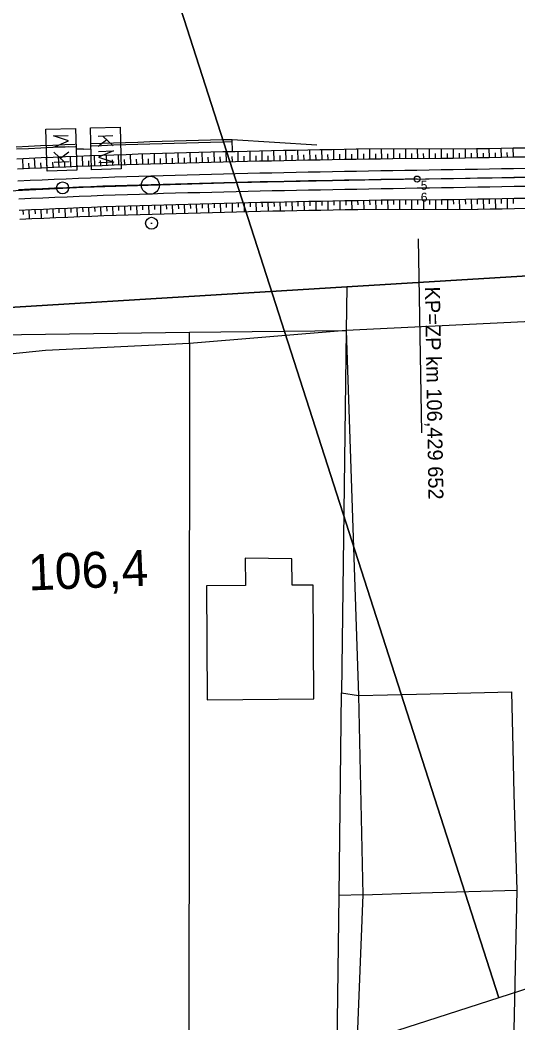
# Model space of a CAD drawing. Extents: x -758836 to -757729, y -1175316 to -1174366.
# Drawn here: x -758212.2 to -758170.6, y -1174834.3 to -1174750.5 of the extents above; entities that cross this region are included whole.
import ezdxf

# ---------------------------------------------------------------- set-up
doc = ezdxf.new("R2010")
doc.units = 0
for name, color, linetype in [('_NOR-návrh tenká', 7, 'Continuous'), ('_NOR-osa', 7, 'Continuous'), ('_NOR-pomocná', 7, 'Continuous'), ('_NOR-popis', 7, 'Continuous'), ('_NOR-svahy', 7, 'Continuous'), ('_NOR-vytyčení', 7, 'Continuous'), ('G_Obvod stavby', 7, 'Continuous'), ('Hranice parcel', 7, 'Continuous'), ('Vrstva 1', 7, 'Continuous'), ('Vrstva 7', 7, 'Continuous')]:
    doc.layers.add(name, color=color, linetype=linetype)

# ---------------------------------------------------------------- blocks, each defined once
blk = doc.blocks.new('C093_1')
at = {"layer": 'Vrstva 7'}
blk.add_line((-0.05, 0), (0.05, 0), dxfattribs=at)
blk.add_circle((0, 0), 0.5, dxfattribs=at)
blk = doc.blocks.new('C513_1')
at = {"layer": 'Vrstva 7'}
blk.add_circle((0, 0), 0.75, dxfattribs=at)
blk = doc.blocks.new('C020')
at = {"layer": 'Vrstva 7'}
for p, q in [((-1.017, 2.489), (-1.017, 1.242)), ((-0.182, 2.489), (-1.017, 1.654)), ((-0.713, 1.959), (-0.182, 1.242)), ((0, 0), (0, 0.623))]:
    blk.add_line(p, q, dxfattribs=at)
blk.add_lwpolyline([(-1.742, 0.623), (-1.742, 3.106), (1.746, 3.106), (1.746, 0.623)], close=True, dxfattribs=at)
blk.add_lwpolyline([(0.23, 1.242), (0.23, 2.489), (0.711, 1.242), (1.182, 2.489), (1.182, 1.242)], dxfattribs=at)
blk = doc.blocks.new('POINT_DISPLAY')
blk.add_line((0, 0), (0, 0))

msp = doc.modelspace()

# ---------------------------------------------------------------- linework, layer by layer
at = {"layer": '_NOR-návrh tenká'}
for p, q in [((-758194.43, -1174761.512), (-758194.453, -1174760.512)), ((-758194.453, -1174760.512), (-758187.38, -1174760.969))]:
    msp.add_line(p, q, dxfattribs=at)
for points in [[(-758212.509, -1174761.123), (-758211.493, -1174761.076), (-758210.477, -1174761.031), (-758209.461, -1174760.987), (-758208.445, -1174760.945), (-758207.581, -1174760.911)], [(-758212.5, -1174761.303), (-758211.484, -1174761.256), (-758210.469, -1174761.211), (-758209.453, -1174761.167), (-758208.438, -1174761.125), (-758207.573, -1174761.091)], [(-758206.238, -1174760.86), (-758205.398, -1174760.83), (-758204.383, -1174760.794), (-758203.368, -1174760.76), (-758202.353, -1174760.727), (-758201.338, -1174760.696), (-758200.324, -1174760.665), (-758199.309, -1174760.636), (-758198.295, -1174760.608), (-758197.281, -1174760.581), (-758196.267, -1174760.556), (-758195.253, -1174760.531), (-758194.453, -1174760.512)], [(-758206.233, -1174761.04), (-758205.392, -1174761.009), (-758204.377, -1174760.974), (-758203.362, -1174760.94), (-758202.347, -1174760.907), (-758201.333, -1174760.875), (-758200.318, -1174760.845), (-758199.304, -1174760.816), (-758198.29, -1174760.788), (-758197.276, -1174760.761), (-758196.262, -1174760.736), (-758195.249, -1174760.711), (-758194.449, -1174760.692)], [(-758212.462, -1174762.122), (-758211.447, -1174762.075), (-758210.433, -1174762.03), (-758209.419, -1174761.986), (-758208.404, -1174761.945), (-758207.39, -1174761.905), (-758206.376, -1174761.866), (-758205.362, -1174761.829), (-758204.349, -1174761.793), (-758203.335, -1174761.759), (-758202.321, -1174761.727), (-758201.308, -1174761.695), (-758200.294, -1174761.665), (-758199.281, -1174761.636), (-758198.268, -1174761.608), (-758197.255, -1174761.581), (-758196.242, -1174761.555), (-758195.229, -1174761.53), (-758194.216, -1174761.507), (-758193.204, -1174761.483), (-758192.191, -1174761.461), (-758191.179, -1174761.44), (-758190.167, -1174761.419), (-758189.154, -1174761.398), (-758188.143, -1174761.379), (-758187.131, -1174761.36), (-758186.119, -1174761.341), (-758185.108, -1174761.322), (-758184.096, -1174761.304), (-758184.038, -1174761.303), (-758174.039, -1174761.282), (-758173.987, -1174761.281), (-758172.977, -1174761.263), (-758171.968, -1174761.245), (-758170.958, -1174761.226), (-758169.949, -1174761.207)], [(-758212.421, -1174762.971), (-758211.409, -1174762.924), (-758210.396, -1174762.879), (-758209.383, -1174762.836), (-758208.37, -1174762.794), (-758207.357, -1174762.754), (-758206.345, -1174762.715), (-758205.332, -1174762.678), (-758204.319, -1174762.643), (-758203.307, -1174762.609), (-758202.294, -1174762.576), (-758201.282, -1174762.545), (-758200.269, -1174762.514), (-758199.257, -1174762.485), (-758198.245, -1174762.458), (-758197.233, -1174762.431), (-758196.221, -1174762.405), (-758195.208, -1174762.38), (-758194.196, -1174762.356), (-758193.185, -1174762.333), (-758192.173, -1174762.311), (-758191.161, -1174762.289), (-758190.149, -1174762.269), (-758189.138, -1174762.248), (-758188.126, -1174762.229), (-758187.115, -1174762.209), (-758186.103, -1174762.191), (-758185.092, -1174762.172), (-758184.081, -1174762.154), (-758183.07, -1174762.137), (-758182.059, -1174762.119), (-758181.048, -1174762.102), (-758181.026, -1174762.101), (-758177.026, -1174762.084), (-758177.005, -1174762.083), (-758175.995, -1174762.066), (-758174.984, -1174762.048), (-758173.974, -1174762.031), (-758172.964, -1174762.013), (-758171.954, -1174761.994), (-758170.944, -1174761.976), (-758169.934, -1174761.957)], [(-758212.374, -1174763.97), (-758211.363, -1174763.923), (-758210.352, -1174763.878), (-758209.341, -1174763.835), (-758208.33, -1174763.793), (-758207.319, -1174763.753), (-758206.308, -1174763.715), (-758205.296, -1174763.678), (-758204.285, -1174763.642), (-758203.274, -1174763.608), (-758202.263, -1174763.576), (-758201.251, -1174763.544), (-758200.24, -1174763.514), (-758199.229, -1174763.485), (-758198.218, -1174763.457), (-758197.207, -1174763.43), (-758196.196, -1174763.405), (-758195.184, -1174763.38), (-758194.173, -1174763.356), (-758193.162, -1174763.333), (-758192.151, -1174763.311), (-758191.14, -1174763.289), (-758190.129, -1174763.268), (-758189.118, -1174763.248), (-758188.107, -1174763.228), (-758187.096, -1174763.209), (-758186.085, -1174763.191), (-758185.074, -1174763.172), (-758184.063, -1174763.154), (-758183.053, -1174763.137), (-758182.042, -1174763.119), (-758181.031, -1174763.102), (-758180.021, -1174763.085), (-758179.01, -1174763.067), (-758177.999, -1174763.05), (-758176.989, -1174763.033), (-758175.978, -1174763.016), (-758174.968, -1174762.998), (-758173.957, -1174762.981), (-758172.947, -1174762.963), (-758171.937, -1174762.944), (-758170.926, -1174762.926), (-758169.916, -1174762.906)], [(-758212.303, -1174765.468), (-758211.295, -1174765.422), (-758210.287, -1174765.377), (-758209.278, -1174765.333), (-758208.269, -1174765.292), (-758207.261, -1174765.252), (-758206.252, -1174765.214), (-758205.243, -1174765.177), (-758204.234, -1174765.141), (-758203.224, -1174765.107), (-758202.215, -1174765.075), (-758201.206, -1174765.044), (-758200.196, -1174765.013), (-758199.187, -1174764.985), (-758198.177, -1174764.957), (-758197.168, -1174764.93), (-758196.158, -1174764.904), (-758195.148, -1174764.879), (-758194.138, -1174764.856), (-758193.129, -1174764.833), (-758192.119, -1174764.81), (-758191.109, -1174764.789), (-758190.098, -1174764.768), (-758189.088, -1174764.748), (-758188.078, -1174764.728), (-758187.068, -1174764.709), (-758186.058, -1174764.69), (-758185.047, -1174764.672), (-758184.037, -1174764.654), (-758183.027, -1174764.636), (-758182.016, -1174764.619), (-758181.006, -1174764.602), (-758179.995, -1174764.584), (-758178.984, -1174764.567), (-758177.974, -1174764.55), (-758176.963, -1174764.533), (-758175.952, -1174764.516), (-758174.942, -1174764.498), (-758173.931, -1174764.48), (-758172.92, -1174764.462), (-758171.909, -1174764.444), (-758170.898, -1174764.425), (-758169.887, -1174764.406)], [(-758212.258, -1174766.417), (-758211.252, -1174766.371), (-758210.245, -1174766.326), (-758209.238, -1174766.283), (-758208.231, -1174766.241), (-758207.224, -1174766.201), (-758206.216, -1174766.163), (-758205.209, -1174766.126), (-758204.201, -1174766.091), (-758203.193, -1174766.057), (-758202.185, -1174766.024), (-758201.177, -1174765.993), (-758200.169, -1174765.963), (-758199.16, -1174765.934), (-758198.152, -1174765.906), (-758197.143, -1174765.88), (-758196.134, -1174765.854), (-758195.125, -1174765.829), (-758194.116, -1174765.805), (-758193.107, -1174765.782), (-758192.098, -1174765.76), (-758191.089, -1174765.739), (-758190.079, -1174765.718), (-758189.07, -1174765.698), (-758188.06, -1174765.678), (-758187.05, -1174765.659), (-758186.04, -1174765.64), (-758185.03, -1174765.622), (-758184.02, -1174765.604), (-758183.01, -1174765.586), (-758182, -1174765.569), (-758180.989, -1174765.551), (-758180.968, -1174765.551), (-758176.968, -1174765.533), (-758176.946, -1174765.533), (-758175.935, -1174765.515), (-758174.924, -1174765.498), (-758173.913, -1174765.48), (-758172.902, -1174765.462), (-758171.891, -1174765.444), (-758170.879, -1174765.425), (-758169.868, -1174765.406)], [(-758212.223, -1174767.166), (-758211.218, -1174767.12), (-758210.212, -1174767.075), (-758209.207, -1174767.032), (-758208.201, -1174766.991), (-758207.195, -1174766.951), (-758206.188, -1174766.912), (-758205.182, -1174766.876), (-758204.175, -1174766.84), (-758203.168, -1174766.807), (-758202.161, -1174766.774), (-758201.154, -1174766.743), (-758200.147, -1174766.713), (-758199.139, -1174766.684), (-758198.131, -1174766.656), (-758197.124, -1174766.629), (-758196.116, -1174766.604), (-758195.107, -1174766.579), (-758194.099, -1174766.555), (-758193.09, -1174766.532), (-758192.082, -1174766.51), (-758191.073, -1174766.488), (-758190.064, -1174766.468), (-758189.055, -1174766.447), (-758188.046, -1174766.428), (-758187.036, -1174766.409), (-758186.027, -1174766.39), (-758185.017, -1174766.372), (-758184.007, -1174766.354), (-758183.955, -1174766.353), (-758173.956, -1174766.331), (-758173.898, -1174766.33), (-758172.887, -1174766.312), (-758171.875, -1174766.294), (-758170.864, -1174766.275), (-758169.852, -1174766.256)]]:
    msp.add_lwpolyline(points, dxfattribs=at)
at = {"layer": '_NOR-osa'}
for points in [[(-758178.997, -1174763.817), (-758177.987, -1174763.8), (-758176.976, -1174763.783), (-758175.965, -1174763.766), (-758174.955, -1174763.748), (-758173.944, -1174763.73), (-758172.933, -1174763.712), (-758171.923, -1174763.694), (-758170.912, -1174763.675), (-758169.902, -1174763.656)], [(-758178.997, -1174763.817), (-758180.008, -1174763.834), (-758181.018, -1174763.852), (-758182.029, -1174763.869), (-758183.04, -1174763.886), (-758184.05, -1174763.904), (-758185.061, -1174763.922), (-758186.071, -1174763.94), (-758187.082, -1174763.959), (-758188.093, -1174763.978), (-758189.103, -1174763.998), (-758190.114, -1174764.018), (-758191.124, -1174764.039), (-758192.135, -1174764.061), (-758193.145, -1174764.083), (-758194.156, -1174764.106), (-758195.166, -1174764.13), (-758196.177, -1174764.154), (-758197.187, -1174764.18), (-758198.198, -1174764.207), (-758199.208, -1174764.235), (-758200.218, -1174764.264), (-758201.229, -1174764.294), (-758202.239, -1174764.325), (-758203.249, -1174764.358), (-758204.259, -1174764.392), (-758205.269, -1174764.427), (-758206.28, -1174764.464), (-758207.29, -1174764.503), (-758208.3, -1174764.543), (-758209.31, -1174764.584), (-758210.319, -1174764.627), (-758211.329, -1174764.672), (-758212.339, -1174764.719)]]:
    msp.add_lwpolyline(points, dxfattribs=at)
msp.add_circle((-758178.997, -1174763.817), 0.25, dxfattribs=at)
msp.add_circle((-758178.997, -1174763.817), 0.25, dxfattribs=at)
at = {"layer": '_NOR-pomocná'}
for points in [[(-758217.708, -1174690.839), (-758117.765, -1174658.647), (-758072.236, -1174799.995), (-758172.179, -1174832.187)], [(-758317.652, -1174723.031), (-758217.708, -1174690.839), (-758172.179, -1174832.187), (-758272.123, -1174864.38)]]:
    msp.add_lwpolyline(points, close=True, dxfattribs=at)
at = {"layer": '_NOR-popis'}
msp.add_line((-758178.912, -1174768.817), (-758178.638, -1174785.011), dxfattribs=at)
msp.add_circle((-758208.639, -1174764.556), 0.5, dxfattribs=at)
at = {"layer": '_NOR-svahy'}
for points in [[(-758209.939, -1174762.859), (-758209.975, -1174762.01)], [(-758208.94, -1174762.817), (-758208.975, -1174761.968)], [(-758207.941, -1174762.777), (-758207.974, -1174761.928)], [(-758206.941, -1174762.738), (-758206.974, -1174761.889)], [(-758205.942, -1174762.701), (-758205.973, -1174761.851)], [(-758204.943, -1174762.665), (-758204.973, -1174761.815)], [(-758203.943, -1174762.63), (-758203.972, -1174761.781)], [(-758202.944, -1174762.597), (-758202.971, -1174761.748)], [(-758201.944, -1174762.565), (-758201.971, -1174761.716)], [(-758200.945, -1174762.535), (-758200.97, -1174761.685)], [(-758199.945, -1174762.505), (-758199.97, -1174761.656)], [(-758198.946, -1174762.477), (-758198.969, -1174761.627)], [(-758197.946, -1174762.45), (-758197.969, -1174761.6)], [(-758197.446, -1174762.436), (-758197.457, -1174762.012)], [(-758196.946, -1174762.424), (-758196.968, -1174761.574)], [(-758196.447, -1174762.411), (-758196.457, -1174761.986)], [(-758195.947, -1174762.398), (-758195.968, -1174761.549)], [(-758195.447, -1174762.386), (-758195.457, -1174761.961)], [(-758194.947, -1174762.374), (-758194.967, -1174761.524)], [(-758194.447, -1174762.362), (-758194.457, -1174761.937)], [(-758193.947, -1174762.351), (-758193.967, -1174761.501)], [(-758193.447, -1174762.339), (-758193.457, -1174761.914)], [(-758192.948, -1174762.328), (-758192.966, -1174761.478)], [(-758192.448, -1174762.317), (-758192.457, -1174761.892)], [(-758191.948, -1174762.306), (-758191.966, -1174761.456)], [(-758191.448, -1174762.296), (-758191.457, -1174761.871)], [(-758190.948, -1174762.285), (-758190.966, -1174761.435)], [(-758190.448, -1174762.275), (-758190.457, -1174761.85)], [(-758189.948, -1174762.264), (-758189.965, -1174761.415)], [(-758189.448, -1174762.254), (-758189.457, -1174761.83)], [(-758188.948, -1174762.245), (-758188.965, -1174761.395)], [(-758188.449, -1174762.235), (-758188.457, -1174761.81)], [(-758187.949, -1174762.225), (-758187.965, -1174761.375)], [(-758187.449, -1174762.216), (-758187.457, -1174761.791)], [(-758186.949, -1174762.206), (-758186.965, -1174761.356)], [(-758186.449, -1174762.197), (-758186.457, -1174761.772)], [(-758185.949, -1174762.188), (-758185.964, -1174761.338)], [(-758185.449, -1174762.179), (-758185.457, -1174761.754)], [(-758184.949, -1174762.17), (-758184.964, -1174761.32)], [(-758184.449, -1174762.161), (-758184.457, -1174761.736)], [(-758183.949, -1174762.152), (-758183.964, -1174761.303)], [(-758183.449, -1174762.143), (-758183.457, -1174761.723)], [(-758182.949, -1174762.135), (-758182.964, -1174761.301)], [(-758182.449, -1174762.126), (-758182.457, -1174761.713)], [(-758181.95, -1174762.117), (-758181.964, -1174761.299)], [(-758181.45, -1174762.109), (-758181.457, -1174761.703)], [(-758180.95, -1174762.101), (-758180.953, -1174761.297)], [(-758180.45, -1174762.099), (-758180.452, -1174761.697)], [(-758179.95, -1174762.097), (-758179.953, -1174761.295)], [(-758179.45, -1174762.094), (-758179.452, -1174761.694)], [(-758178.95, -1174762.092), (-758178.953, -1174761.292)], [(-758178.45, -1174762.09), (-758178.452, -1174761.691)], [(-758177.95, -1174762.088), (-758177.953, -1174761.29)], [(-758177.45, -1174762.085), (-758177.452, -1174761.687)], [(-758176.95, -1174762.082), (-758176.963, -1174761.288)], [(-758176.45, -1174762.074), (-758176.457, -1174761.68)], [(-758175.95, -1174762.065), (-758175.963, -1174761.286)], [(-758175.45, -1174762.056), (-758175.457, -1174761.671)], [(-758174.95, -1174762.048), (-758174.963, -1174761.284)], [(-758174.45, -1174762.039), (-758174.457, -1174761.661)], [(-758173.95, -1174762.03), (-758173.964, -1174761.28)], [(-758173.45, -1174762.021), (-758173.457, -1174761.646)], [(-758172.95, -1174762.013), (-758172.964, -1174761.263)], [(-758172.45, -1174762.003), (-758172.457, -1174761.629)], [(-758171.951, -1174761.994), (-758171.964, -1174761.245)], [(-758171.451, -1174761.985), (-758171.458, -1174761.61)], [(-758170.951, -1174761.976), (-758170.965, -1174761.226)], [(-758211.937, -1174762.949), (-758211.976, -1174762.1)], [(-758211.437, -1174762.926), (-758211.457, -1174762.501)], [(-758210.938, -1174762.903), (-758210.976, -1174762.054)], [(-758210.438, -1174762.881), (-758210.457, -1174762.456)], [(-758209.439, -1174762.838), (-758209.458, -1174762.413)], [(-758208.44, -1174762.797), (-758208.458, -1174762.372)], [(-758207.441, -1174762.757), (-758207.458, -1174762.333)], [(-758206.442, -1174762.719), (-758206.458, -1174762.294)], [(-758205.442, -1174762.682), (-758205.458, -1174762.258)], [(-758204.443, -1174762.647), (-758204.458, -1174762.223)], [(-758203.444, -1174762.613), (-758203.458, -1174762.189)], [(-758202.444, -1174762.581), (-758202.458, -1174762.156)], [(-758201.445, -1174762.55), (-758201.458, -1174762.125)], [(-758200.445, -1174762.52), (-758200.458, -1174762.095)], [(-758199.445, -1174762.491), (-758199.458, -1174762.066)], [(-758198.446, -1174762.463), (-758198.458, -1174762.038)], [(-758207.463, -1174766.211), (-758207.433, -1174766.96)], [(-758206.963, -1174766.191), (-758206.949, -1174766.566)], [(-758206.464, -1174766.172), (-758206.435, -1174766.922)], [(-758205.964, -1174766.154), (-758205.95, -1174766.529)], [(-758205.464, -1174766.136), (-758205.437, -1174766.885)], [(-758204.965, -1174766.118), (-758204.952, -1174766.492)], [(-758204.465, -1174766.1), (-758204.439, -1174766.85)], [(-758203.965, -1174766.083), (-758203.953, -1174766.458)], [(-758203.466, -1174766.066), (-758203.44, -1174766.816)], [(-758202.966, -1174766.05), (-758202.954, -1174766.424)], [(-758202.466, -1174766.033), (-758202.442, -1174766.783)], [(-758201.966, -1174766.018), (-758201.955, -1174766.392)], [(-758201.467, -1174766.002), (-758201.443, -1174766.752)], [(-758200.967, -1174765.987), (-758200.956, -1174766.362)], [(-758200.467, -1174765.972), (-758200.445, -1174766.722)], [(-758199.967, -1174765.957), (-758199.957, -1174766.332)], [(-758199.468, -1174765.943), (-758199.446, -1174766.693)], [(-758198.968, -1174765.929), (-758198.957, -1174766.304)], [(-758198.468, -1174765.915), (-758198.447, -1174766.665)], [(-758197.968, -1174765.902), (-758197.958, -1174766.276)], [(-758197.468, -1174765.888), (-758197.448, -1174766.638)], [(-758196.968, -1174765.875), (-758196.959, -1174766.25)], [(-758196.469, -1174765.862), (-758196.45, -1174766.612)], [(-758195.969, -1174765.85), (-758195.96, -1174766.225)], [(-758195.469, -1174765.838), (-758195.451, -1174766.587)], [(-758194.969, -1174765.826), (-758194.96, -1174766.2)], [(-758194.469, -1174765.814), (-758194.452, -1174766.563)], [(-758193.969, -1174765.802), (-758193.961, -1174766.177)], [(-758193.469, -1174765.791), (-758193.452, -1174766.54)], [(-758192.97, -1174765.779), (-758192.961, -1174766.154)], [(-758192.47, -1174765.768), (-758192.453, -1174766.518)], [(-758191.97, -1174765.757), (-758191.962, -1174766.132)], [(-758191.47, -1174765.747), (-758191.454, -1174766.497)], [(-758190.97, -1174765.736), (-758190.962, -1174766.111)], [(-758190.47, -1174765.726), (-758190.455, -1174766.476)], [(-758189.97, -1174765.716), (-758189.963, -1174766.091)], [(-758189.47, -1174765.706), (-758189.455, -1174766.455)], [(-758188.97, -1174765.696), (-758188.963, -1174766.071)], [(-758188.471, -1174765.686), (-758188.456, -1174766.436)], [(-758187.971, -1174765.676), (-758187.964, -1174766.051)], [(-758187.471, -1174765.667), (-758187.457, -1174766.417)], [(-758186.971, -1174765.657), (-758186.964, -1174766.032)], [(-758186.471, -1174765.648), (-758186.457, -1174766.398)], [(-758185.971, -1174765.639), (-758185.964, -1174766.014)], [(-758185.471, -1174765.63), (-758185.458, -1174766.38)], [(-758184.971, -1174765.621), (-758184.965, -1174765.996)], [(-758184.471, -1174765.612), (-758184.458, -1174766.362)], [(-758183.971, -1174765.603), (-758183.965, -1174765.978)], [(-758183.471, -1174765.594), (-758183.458, -1174766.352)], [(-758182.972, -1174765.585), (-758182.965, -1174765.968)], [(-758182.472, -1174765.577), (-758182.458, -1174766.35)], [(-758181.972, -1174765.568), (-758181.965, -1174765.958)], [(-758181.472, -1174765.56), (-758181.458, -1174766.347)], [(-758180.972, -1174765.551), (-758180.965, -1174765.949)], [(-758180.472, -1174765.549), (-758180.468, -1174766.345)], [(-758179.972, -1174765.547), (-758179.97, -1174765.945)], [(-758179.472, -1174765.544), (-758179.468, -1174766.343)], [(-758178.972, -1174765.542), (-758178.97, -1174765.942)], [(-758178.472, -1174765.54), (-758178.468, -1174766.341)], [(-758177.972, -1174765.538), (-758177.97, -1174765.939)], [(-758177.472, -1174765.535), (-758177.468, -1174766.339)], [(-758176.972, -1174765.533), (-758176.97, -1174765.935)], [(-758176.472, -1174765.525), (-758176.458, -1174766.337)], [(-758175.972, -1174765.516), (-758175.965, -1174765.926)], [(-758175.472, -1174765.507), (-758175.458, -1174766.334)], [(-758174.972, -1174765.499), (-758174.965, -1174765.916)], [(-758174.472, -1174765.49), (-758174.457, -1174766.332)], [(-758173.972, -1174765.481), (-758173.965, -1174765.906)], [(-758173.472, -1174765.472), (-758173.457, -1174766.322)], [(-758172.972, -1174765.463), (-758172.965, -1174765.888)], [(-758172.473, -1174765.454), (-758172.457, -1174766.304)], [(-758171.973, -1174765.445), (-758171.965, -1174765.87)], [(-758171.473, -1174765.436), (-758171.457, -1174766.286)], [(-758170.973, -1174765.427), (-758170.965, -1174765.852)], [(-758211.959, -1174766.403), (-758211.942, -1174766.778)], [(-758211.459, -1174766.38), (-758211.425, -1174767.129)], [(-758210.96, -1174766.358), (-758210.943, -1174766.732)], [(-758210.46, -1174766.335), (-758210.427, -1174767.085)], [(-758209.961, -1174766.314), (-758209.945, -1174766.688)], [(-758209.461, -1174766.292), (-758209.429, -1174767.041)], [(-758208.962, -1174766.271), (-758208.946, -1174766.646)], [(-758208.462, -1174766.251), (-758208.431, -1174767)], [(-758207.963, -1174766.231), (-758207.948, -1174766.605)]]:
    msp.add_lwpolyline(points, dxfattribs=at)
at = {"layer": 'G_Obvod stavby'}
msp.add_lwpolyline([(-758392.72, -1174840.756), (-758391.23, -1174838.56), (-758368.37, -1174821.64), (-758340.31, -1174807.33), (-758320.27, -1174796.89), (-758301, -1174790.21), (-758267.96, -1174782.93), (-758224.96, -1174775.27), (-758184.87, -1174772.83), (-758142.71, -1174770.26), (-758089.84, -1174768.68), (-758106.02, -1174731.44), (-758149.09, -1174725.67), (-758199.62, -1174726.6), (-758225.76, -1174732.36), (-758252.17, -1174738.18), (-758254.97, -1174739.34), (-758266.58, -1174744.16), (-758279.45, -1174749.49), (-758302.42, -1174759.02), (-758331.68, -1174770.24), (-758367.17, -1174799.81), (-758405.64, -1174832.2)], dxfattribs=at)
at = {"layer": 'Hranice parcel'}
for p, q in [((-758184.87, -1174772.83), (-758184.92, -1174776.46)), ((-758225.62, -1174776.96), (-758198.02, -1174776.62)), ((-758184.92, -1174776.46), (-758198.02, -1174777.55)), ((-758198.02, -1174776.62), (-758184.92, -1174776.46)), ((-758198.02, -1174777.55), (-758198.02, -1174776.62)), ((-758184.92, -1174776.46), (-758185.31, -1174806.74)), ((-758184.92, -1174776.46), (-758183.9, -1174806.95)), ((-758185.53, -1174823.65), (-758185.31, -1174806.74)), ((-758185.31, -1174806.74), (-758183.9, -1174806.95)), ((-758183.9, -1174806.95), (-758183.53, -1174823.59)), ((-758186.22, -1174876.87), (-758185.53, -1174823.65)), ((-758183.53, -1174823.59), (-758185.73, -1174876.96)), ((-758183.53, -1174823.59), (-758185.53, -1174823.65)), ((-758170.66, -1174823.2), (-758171.67, -1174870.63))]:
    msp.add_line(p, q, dxfattribs=at)
for points in [[(-757877.73, -1174631.24), (-757883.07, -1174637.8), (-757892.39, -1174640.95), (-757964.85, -1174709.42), (-757976.05, -1174741.17), (-757981.89, -1174745.86), (-757990.29, -1174747.68), (-757997.69, -1174745.08), (-758004.14, -1174738), (-758040.32, -1174755.99), (-758089.84, -1174768.68), (-758142.71, -1174770.26), (-758184.87, -1174772.83)], [(-758184.87, -1174772.83), (-758224.96, -1174775.27), (-758267.96, -1174782.93), (-758301, -1174790.21), (-758320.27, -1174796.89)], [(-758156.63, -1174775.13), (-758157.99, -1174775.16), (-758184.92, -1174776.46)], [(-758198.02, -1174777.55), (-758210.07, -1174778.13), (-758217.96, -1174778.94)], [(-758198.02, -1174777.55), (-758198.11, -1174871.18), (-758198.12, -1174878.49)], [(-758196.6, -1174797.79), (-758196.54, -1174807.31), (-758187.63, -1174807.24), (-758187.69, -1174797.73), (-758189.45, -1174797.74), (-758189.47, -1174795.54), (-758193.37, -1174795.47), (-758193.36, -1174797.77), (-758196.6, -1174797.79)], [(-758183.9, -1174806.95), (-758179.06, -1174806.83), (-758171.11, -1174806.65), (-758171, -1174811.35), (-758170.9, -1174815.15), (-758170.66, -1174823.2)], [(-758183.53, -1174823.59), (-758178.71, -1174823.44), (-758170.66, -1174823.2)]]:
    msp.add_lwpolyline(points, dxfattribs=at)
at = {"layer": 'Vrstva 1'}
msp.add_lwpolyline([(-758275.047, -1174773.289), (-758265.484, -1174771.118), (-758253.61, -1174768.888), (-758243.69, -1174767.426), (-758231.371, -1174766.042), (-758219.363, -1174765.122), (-758206.915, -1174764.505), (-758194.225, -1174764.118), (-758182.013, -1174763.871), (-758170.862, -1174763.683), (-758162.019, -1174763.496), (-758153.195, -1174763.228), (-758152.069, -1174763.19), (-758141.836, -1174762.716), (-758130.402, -1174761.933), (-758120.726, -1174760.981), (-758108.612, -1174759.398), (-758096.467, -1174757.277), (-758085.591, -1174754.917)], dxfattribs=at)

# ---------------------------------------------------------------- block references
at = {"layer": '_NOR-vytyčení'}
msp.add_blockref('POINT_DISPLAY', (-758178.997, -1174763.817), dxfattribs=at)
msp.add_blockref('POINT_DISPLAY', (-758178.997, -1174763.817), dxfattribs=at)
at = {"layer": 'Vrstva 7'}
for name, p, rotation in [('C020', (-758206.89, -1174761.314), -88.25322328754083), ('C020', (-758206.89, -1174761.314), 91.74677671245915), ('C513_1', (-758201.302, -1174764.334), 1.7467767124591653), ('C093_1', (-758201.201, -1174767.514), 1.7467767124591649)]:
    msp.add_blockref(name, p, dxfattribs=dict(at, rotation=rotation))

# ---------------------------------------------------------------- texts
at = {"layer": '_NOR-popis'}
for s, height, rotation, p in [('KP=ZP km 106,429 652', 1.25, 270.97093, (-758178.345, -1174772.808)), ('106,4', 3, 2.3427, (-758211.462, -1174798.184))]:
    msp.add_text(s, height=height, rotation=rotation, dxfattribs=at).set_placement(p)
at = {"layer": '_NOR-vytyčení'}
for s, p in [('5', (-758178.697, -1174764.717)), ('6', (-758178.691, -1174765.708))]:
    msp.add_text(s, height=0.75, rotation=360, dxfattribs=at).set_placement(p)

doc.saveas('drawing.dxf')
